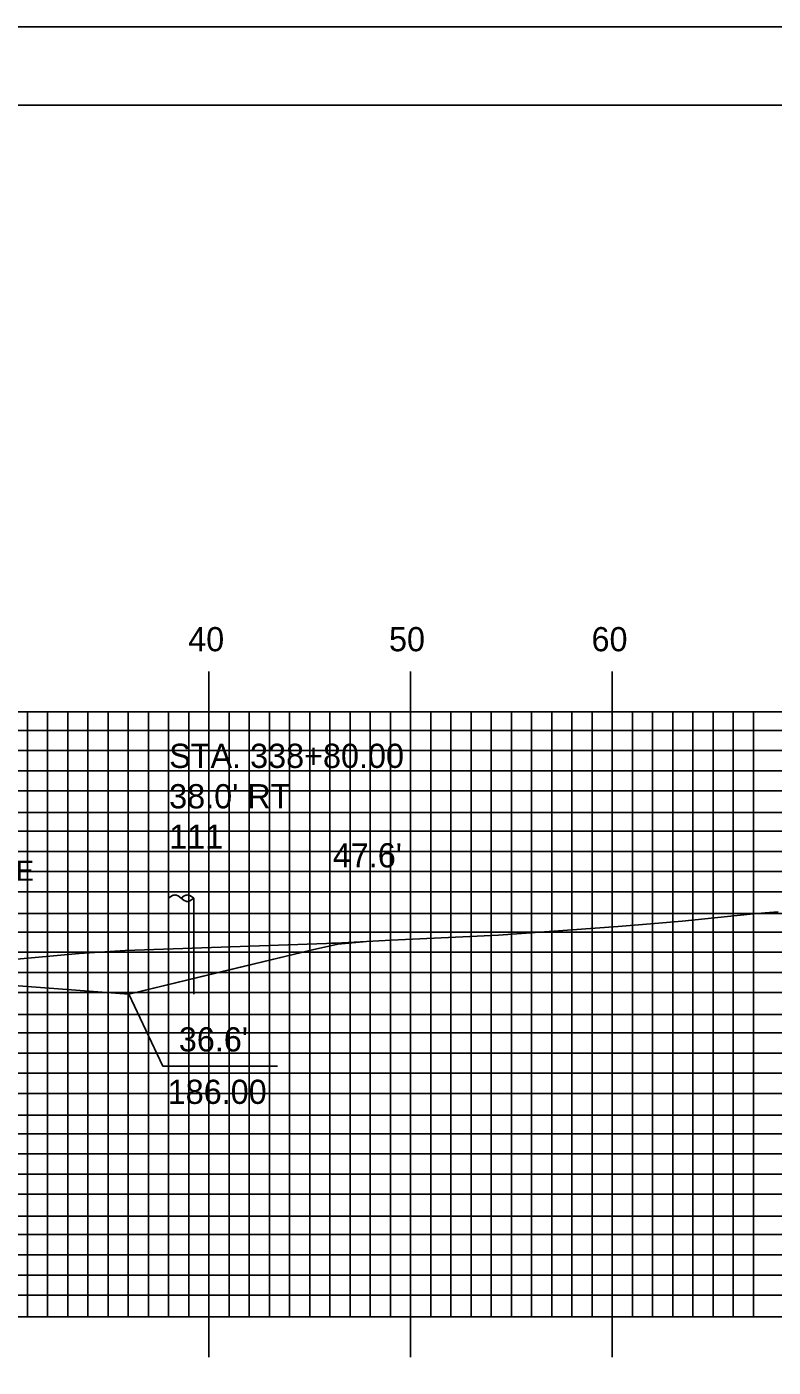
# Model space of a CAD drawing. Extents: x 1823966 to 1824309, y 442591 to 442811.
# Drawn here: x 1824162.8 to 1824199.8, y 442744.1 to 442810.5 of the extents above; entities that cross this region are included whole.
import ezdxf

# ---------------------------------------------------------------- set-up
doc = ezdxf.new("R2010")
doc.units = 0
for name, color, linetype in [('ANNOTATION', 7, 'Continuous'), ('BORDER', 7, 'Continuous'), ('D_Drainage_Text', 7, 'Continuous'), ('D_Roadway_Centerline', 7, 'Continuous'), ('D_Text_Monospaced', 7, 'Continuous'), ('D_Text_Standard', 7, 'Continuous'), ('D_Utilities_Pole_Joint', 7, 'Continuous'), ('H_V ANNOTATION', 7, 'Continuous'), ('MAJOR', 7, 'Continuous'), ('MINOR', 7, 'Continuous'), ('PLOT BOUNDARY', 7, 'Continuous'), ('S_Roadway_Centerline', 7, 'Continuous')]:
    doc.layers.add(name, color=color, linetype=linetype)

msp = doc.modelspace()

# ---------------------------------------------------------------- linework, layer by layer
at = {"layer": 'ANNOTATION'}
for points in [[(1824158.422, 442763.301), (1824167.853, 442762.587), (1824176.965, 442764.792)], [(1824175.223, 442759.022), (1824169.531, 442759.022), (1824167.853, 442762.587)]]:
    msp.add_lwpolyline(points, dxfattribs=at)
at = {"layer": 'BORDER'}
msp.add_lwpolyline([(1823982.222, 442596.665), (1824302.222, 442596.665), (1824302.222, 442806.665), (1823982.222, 442806.665)], close=True, dxfattribs=at)
at = {"layer": 'D_Roadway_Centerline'}
msp.add_lwpolyline([(1824101.648, 442760.592), (1824108.628, 442762.337), (1824111.822, 442763.135), (1824119.822, 442763.455), (1824131.822, 442763.695), (1824143.822, 442763.455), (1824151.822, 442763.135), (1824157.822, 442763.255), (1824158.422, 442763.301), (1824167.853, 442762.587), (1824172.409, 442763.689), (1824176.965, 442764.792), (1824176.965, 442764.792), (1824178.215, 442765.061), (1824179.465, 442765.188)], dxfattribs=at)
at = {"layer": 'D_Utilities_Pole_Joint'}
for p, q in [((1824169.822, 442767.346), (1824169.978, 442767.456)), ((1824169.822, 442762.588), (1824169.822, 442767.346)), ((1824170.29, 442767.456), (1824170.446, 442767.346)), ((1824170.603, 442767.456), (1824170.446, 442767.346)), ((1824170.446, 442767.346), (1824170.603, 442767.235)), ((1824171.072, 442767.346), (1824170.916, 442767.456)), ((1824170.916, 442767.235), (1824171.072, 442767.346)), ((1824171.072, 442762.588), (1824171.072, 442767.346))]:
    msp.add_line(p, q, dxfattribs=at)
for centre, start, end in [((1824170.134, 442767.235), 90, 125.26439), ((1824170.134, 442767.235), 54.73561, 90), ((1824170.759, 442767.235), 90, 125.26439), ((1824170.759, 442767.235), 54.73561, 90), ((1824170.759, 442767.456), 234.73561, 270), ((1824170.759, 442767.456), 270, 305.26439)]:
    msp.add_arc(centre, 0.271, start, end, dxfattribs=at)
at = {"layer": 'MAJOR'}
for p, q in [((1824171.822, 442778.592), (1824171.822, 442776.588)), ((1824181.822, 442778.592), (1824181.822, 442776.588)), ((1824191.822, 442778.592), (1824191.822, 442776.588)), ((1823991.822, 442776.588), (1824271.822, 442776.588)), ((1824171.822, 442746.588), (1824171.822, 442776.588)), ((1824181.822, 442746.588), (1824181.822, 442776.588)), ((1824191.822, 442746.588), (1824191.822, 442776.588)), ((1823991.822, 442771.588), (1824271.822, 442771.588)), ((1823991.822, 442766.588), (1824271.822, 442766.588)), ((1823991.822, 442761.588), (1824271.822, 442761.588)), ((1823991.822, 442756.588), (1824271.822, 442756.588)), ((1823991.822, 442751.588), (1824271.822, 442751.588)), ((1823991.822, 442746.588), (1824271.822, 442746.588)), ((1823991.822, 442746.588), (1824271.822, 442746.588)), ((1824171.822, 442744.584), (1824171.822, 442746.588)), ((1824181.822, 442744.584), (1824181.822, 442746.588)), ((1824191.822, 442744.584), (1824191.822, 442746.588))]:
    msp.add_line(p, q, dxfattribs=at)
at = {"layer": 'MINOR'}
for p, q in [((1824162.822, 442746.588), (1824162.822, 442776.588)), ((1824163.822, 442746.588), (1824163.822, 442776.588)), ((1824164.822, 442746.588), (1824164.822, 442776.588)), ((1824165.822, 442746.588), (1824165.822, 442776.588)), ((1824166.822, 442746.588), (1824166.822, 442776.588)), ((1824167.822, 442746.588), (1824167.822, 442776.588)), ((1824168.822, 442746.588), (1824168.822, 442776.588)), ((1824169.822, 442746.588), (1824169.822, 442776.588)), ((1824170.822, 442746.588), (1824170.822, 442776.588)), ((1824172.822, 442746.588), (1824172.822, 442776.588)), ((1824173.822, 442746.588), (1824173.822, 442776.588)), ((1824174.822, 442746.588), (1824174.822, 442776.588)), ((1824175.822, 442746.588), (1824175.822, 442776.588)), ((1824176.822, 442746.588), (1824176.822, 442776.588)), ((1824177.822, 442746.588), (1824177.822, 442776.588)), ((1824178.822, 442746.588), (1824178.822, 442776.588)), ((1824179.822, 442746.588), (1824179.822, 442776.588)), ((1824180.822, 442746.588), (1824180.822, 442776.588)), ((1824182.822, 442746.588), (1824182.822, 442776.588)), ((1824183.822, 442746.588), (1824183.822, 442776.588)), ((1824184.822, 442746.588), (1824184.822, 442776.588)), ((1824185.822, 442746.588), (1824185.822, 442776.588)), ((1824186.822, 442746.588), (1824186.822, 442776.588)), ((1824187.822, 442746.588), (1824187.822, 442776.588)), ((1824188.822, 442746.588), (1824188.822, 442776.588)), ((1824189.822, 442746.588), (1824189.822, 442776.588)), ((1824190.822, 442746.588), (1824190.822, 442776.588)), ((1824192.822, 442746.588), (1824192.822, 442776.588)), ((1824193.822, 442746.588), (1824193.822, 442776.588)), ((1824194.822, 442746.588), (1824194.822, 442776.588)), ((1824195.822, 442746.588), (1824195.822, 442776.588)), ((1824196.822, 442746.588), (1824196.822, 442776.588)), ((1824197.822, 442746.588), (1824197.822, 442776.588)), ((1824198.822, 442746.588), (1824198.822, 442776.588)), ((1823991.822, 442775.665), (1824271.822, 442775.665)), ((1823991.822, 442774.665), (1824271.822, 442774.665)), ((1823991.822, 442773.665), (1824271.822, 442773.665)), ((1823991.822, 442772.665), (1824271.822, 442772.665)), ((1823991.822, 442770.665), (1824271.822, 442770.665)), ((1823991.822, 442769.665), (1824271.822, 442769.665)), ((1823991.822, 442768.665), (1824271.822, 442768.665)), ((1823991.822, 442767.665), (1824271.822, 442767.665)), ((1823991.822, 442765.665), (1824271.822, 442765.665)), ((1823991.822, 442764.665), (1824271.822, 442764.665)), ((1823991.822, 442763.665), (1824271.822, 442763.665)), ((1823991.822, 442762.665), (1824271.822, 442762.665)), ((1823991.822, 442760.665), (1824271.822, 442760.665)), ((1823991.822, 442759.665), (1824271.822, 442759.665)), ((1823991.822, 442758.665), (1824271.822, 442758.665)), ((1823991.822, 442757.665), (1824271.822, 442757.665)), ((1823991.822, 442755.665), (1824271.822, 442755.665)), ((1823991.822, 442754.665), (1824271.822, 442754.665)), ((1823991.822, 442753.665), (1824271.822, 442753.665)), ((1823991.822, 442752.665), (1824271.822, 442752.665)), ((1823991.822, 442750.665), (1824271.822, 442750.665)), ((1823991.822, 442749.665), (1824271.822, 442749.665)), ((1823991.822, 442748.665), (1824271.822, 442748.665)), ((1823991.822, 442747.665), (1824271.822, 442747.665))]:
    msp.add_line(p, q, dxfattribs=at)
at = {"layer": 'PLOT BOUNDARY'}
msp.add_lwpolyline([(1823966.035, 442590.547), (1824306.035, 442590.547), (1824306.035, 442810.547), (1823966.035, 442810.547)], close=True, dxfattribs=at)
at = {"layer": 'S_Roadway_Centerline'}
msp.add_lwpolyline([(1824158.811, 442764.002), (1824165.394, 442764.598), (1824167.677, 442764.755), (1824177.649, 442765.1), (1824177.897, 442765.11), (1824177.919, 442765.103), (1824177.92, 442765.109), (1824178.119, 442765.119), (1824180.864, 442765.259), (1824186.177, 442765.514), (1824192.11, 442765.943), (1824193.913, 442766.094), (1824195.281, 442766.213), (1824198.653, 442766.561), (1824199.405, 442766.625), (1824200.049, 442766.674)], dxfattribs=at)

# ---------------------------------------------------------------- texts
at = {"layer": 'ANNOTATION'}
for s, p in [("36.6'", (1824170.33, 442759.748)), ('186.00', (1824169.779, 442757.148))]:
    msp.add_text(s, height=1.2, dxfattribs=at).set_placement(p)
at = {"layer": 'D_Drainage_Text'}
for s, p in [('STA. 338+80.00', (1824169.852, 442773.804)), ("38.0' RT", (1824169.852, 442771.8)), ('111', (1824169.852, 442769.796))]:
    msp.add_text(s, height=1.2, dxfattribs=at).set_placement(p)
at = {"layer": 'D_Text_Monospaced'}
msp.add_text('EXIST. 32" PINE', height=0.99996, dxfattribs=at).set_placement((1824153.082, 442768.208))
at = {"layer": 'D_Text_Standard'}
msp.add_text("47.6'", height=1.2, dxfattribs=at).set_placement((1824177.965, 442768.872))
at = {"layer": 'H_V ANNOTATION'}
for s, p in [('40', (1824170.794, 442779.588)), ('50', (1824180.751, 442779.588)), ('60', (1824190.794, 442779.588))]:
    msp.add_text(s, height=1.2, dxfattribs=at).set_placement(p)

doc.saveas('drawing.dxf')
